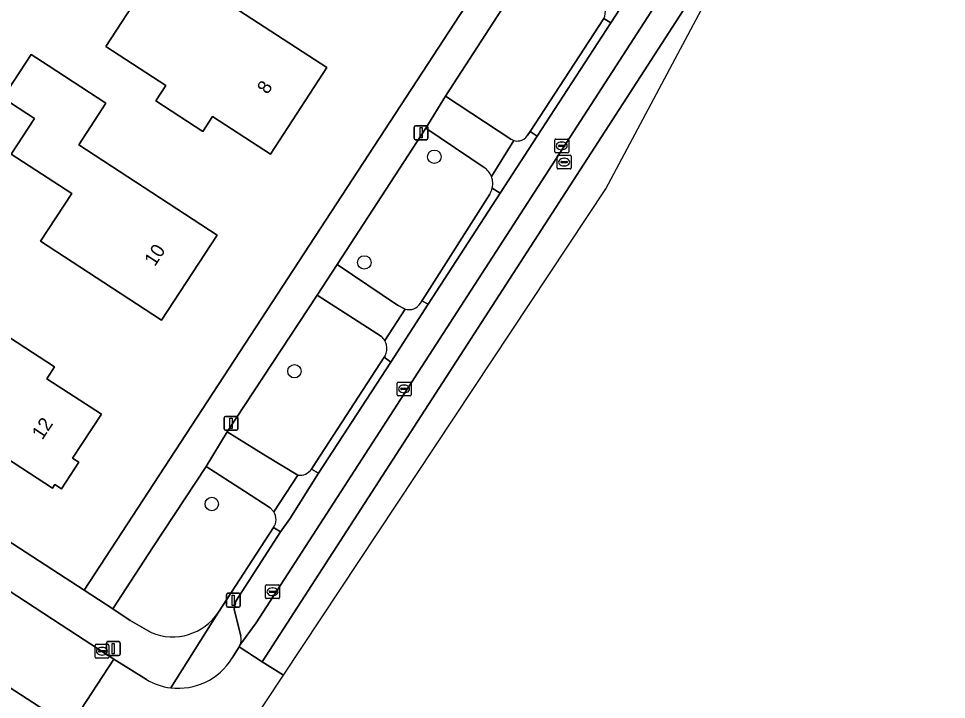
# Model space of a CAD drawing. Extents: x 161139 to 161601, y 381708 to 382245.
# Drawn here: x 161518.7 to 161586, y 382032.9 to 382082.4 of the extents above; entities that cross this region are included whole.
import ezdxf

# ---------------------------------------------------------------- set-up
doc = ezdxf.new("R2010")
doc.units = 0
for name, color, linetype in [('IMGEO_Boom', 7, 'Continuous'), ('IMGEO_Erf', 7, 'Continuous'), ('IMGEO_Groenvoorziening', 7, 'Continuous'), ('IMGEO_Kolk', 7, 'Continuous'), ('IMGEO_Lichtmast', 7, 'Continuous'), ('IMGEO_Pand', 7, 'Continuous'), ('IMGEO_Pand_nummerreeks', 7, 'Continuous'), ('IMGEO_Parkeervlak_open', 7, 'Continuous'), ('IMGEO_Rijbaan_lokaal_gesloten', 7, 'Continuous'), ('IMGEO_Rijbaan_lokaal_open', 7, 'Continuous'), ('IMGEO_Rioolput', 7, 'Continuous'), ('IMGEO_Voetpad_open', 7, 'Continuous')]:
    doc.layers.add(name, color=color, linetype=linetype)

msp = doc.modelspace()

# ---------------------------------------------------------------- linework, layer by layer
at = {"layer": 'IMGEO_Boom'}
for centre in [(161548.856, 382072.342), (161543.772, 382064.666), (161538.702, 382056.761), (161532.7, 382047.114)]:
    msp.add_circle(centre, 0.489, dxfattribs=at)
at = {"layer": 'IMGEO_Erf'}
msp.add_lwpolyline([(161553.295, 382144.911), (161544.61, 382147.101), (161500, 382158.072), (161477.956, 382163.494), (161457.897, 382168.303), (161418.52, 382178.097), (161389.844, 382185.251), (161387.058, 382185.651), (161384.186, 382184.996), (161381.949, 382183.375), (161380.259, 382181.034), (161377.586, 382172.934), (161374.321, 382163.969), (161372.26, 382158.835), (161369.98, 382153.637), (161365.084, 382143.565), (161365.175, 382143.293), (161389.855, 382127.317), (161408.789, 382114.947), (161450.498, 382088.211), (161500, 382056.07), (161523.437, 382040.853), (161561.628, 382099.383), (161581.409, 382129.761)], dxfattribs=at)
for points in [[(161527.701, 382084.489), (161521.198, 382088.726), (161524.545, 382093.864), (161525.651, 382093.143), (161529.841, 382090.414), (161527.88, 382087.405), (161541.06, 382078.818), (161536.96, 382072.525), (161532.764, 382075.259), (161532.059, 382074.178), (161528.63, 382076.412), (161529.353, 382077.522), (161525.007, 382080.354)], [(161525.013, 382076.229), (161523.049, 382073.199), (161533.095, 382066.653), (161529.061, 382060.463), (161524.873, 382063.195), (161520.269, 382066.197), (161522.531, 382069.665), (161518.135, 382072.533), (161519.823, 382075.12), (161517.521, 382076.623), (161519.575, 382079.772), (161520.824, 382078.958)], [(161513.814, 382065.857), (161512.023, 382063.108), (161521.288, 382057.068), (161520.733, 382056.215), (161524.682, 382053.642), (161522.592, 382050.435), (161523.042, 382050.142), (161521.792, 382048.223), (161521.315, 382048.534), (161521.136, 382048.26), (161512.05, 382054.18), (161513.345, 382056.167), (161510.877, 382057.775), (161511.727, 382059.08), (161510.091, 382060.146), (161509.99, 382059.992), (161504.545, 382063.541), (161505.105, 382064.4), (161502.144, 382066.33), (161505.406, 382071.336), (161508.368, 382069.406)]]:
    msp.add_lwpolyline(points, close=True, dxfattribs=at)
at = {"layer": 'IMGEO_Groenvoorziening'}
for points in [[(161560.731, 382083.685), (161556.061, 382086.613), (161549.678, 382076.751), (161554.422, 382073.613)], [(161555.605, 382073.86), (161555.805, 382074.166), (161561.16, 382082.381)], [(161552.488, 382071.564), (161548.238, 382074.428), (161541.805, 382064.505), (161546.19, 382061.555), (161546.737, 382061.267)], [(161547.846, 382061.711), (161547.959, 382061.886), (161548.022, 382061.982), (161552.884, 382069.618)], [(161545.028, 382059.277), (161540.355, 382062.295), (161533.813, 382052.367), (161536.622, 382050.604), (161538.946, 382049.208)], [(161539.95, 382049.657), (161540.282, 382050.166), (161545.221, 382057.781), (161545.289, 382057.886)], [(161537.207, 382046.547), (161536.938, 382046.844), (161535.064, 382048.048), (161532.291, 382049.829), (161528.456, 382043.995), (161525.518, 382039.495), (161526.784, 382038.653), (161528.309, 382037.772)], [(161533.184, 382039.253), (161537.192, 382045.404)]]:
    msp.add_lwpolyline(points, dxfattribs=at)
for centre, radius, start, end in [((161560.344, 382082.836), 0.935, 330.87903, 17.06204), ((161554.905, 382074.414), 0.935, 238.91578, 253.55001), ((161554.881, 382074.367), 0.883, 254.13744, 281.46792), ((161554.889, 382074.356), 0.871, 281.1415, 325.31688), ((161551.671, 382070.392), 1.429, 20.73963, 55.11747), ((161551.663, 382070.381), 1.44, 7.97325, 21.03293), ((161551.649, 382070.382), 1.452, 328.26453, 347.19705), ((161551.615, 382070.388), 1.487, 347.26233, 7.46271), ((161546.998, 382062.222), 0.99, 254.73036, 328.90808), ((161544.234, 382058.419), 1.169, 28.84853, 47.22454), ((161544.246, 382058.412), 1.162, 13.02195, 29.42536), ((161544.201, 382058.408), 1.207, 334.38025, 12.73192), ((161539.075, 382050.267), 1.067, 263.0652, 325.12425), ((161536.289, 382045.987), 1.075, 327.13152, 31.36474), ((161529.854, 382041.45), 3.989, 247.21393, 326.58309)]:
    msp.add_arc(centre, radius, start, end, dxfattribs=at)
at = {"layer": 'IMGEO_Kolk'}
for p, q in [((161557.611, 382072.704), (161557.611, 382073.556)), ((161557.686, 382073.63), (161558.538, 382073.63)), ((161558.099, 382073.41), (161558.124, 382073.41)), ((161558.612, 382073.556), (161558.612, 382072.704)), ((161557.87, 382073.124), (161557.87, 382073.136)), ((161558.308, 382073.087), (161557.91, 382073.087)), ((161557.913, 382073.173), (161558.311, 382073.173)), ((161558.122, 382072.85), (161558.097, 382072.85)), ((161558.354, 382073.136), (161558.354, 382073.124)), ((161558.538, 382072.63), (161557.686, 382072.63)), ((161546.165, 382055.049), (161546.165, 382055.901)), ((161546.24, 382055.975), (161547.092, 382055.975)), ((161547.166, 382055.901), (161547.166, 382055.049)), ((161546.424, 382055.469), (161546.424, 382055.481)), ((161546.862, 382055.432), (161546.464, 382055.432)), ((161546.467, 382055.518), (161546.865, 382055.518)), ((161546.676, 382055.195), (161546.651, 382055.195)), ((161546.653, 382055.755), (161546.678, 382055.755)), ((161546.908, 382055.481), (161546.908, 382055.469)), ((161547.092, 382054.975), (161546.24, 382054.975)), ((161536.607, 382040.314), (161536.607, 382041.166)), ((161536.682, 382041.24), (161537.534, 382041.24)), ((161537.095, 382041.02), (161537.12, 382041.02)), ((161537.608, 382041.166), (161537.608, 382040.314)), ((161536.866, 382040.734), (161536.866, 382040.746)), ((161537.304, 382040.697), (161536.906, 382040.697)), ((161536.909, 382040.783), (161537.307, 382040.783)), ((161537.118, 382040.46), (161537.093, 382040.46)), ((161537.35, 382040.746), (161537.35, 382040.734)), ((161537.534, 382040.24), (161536.682, 382040.24)), ((161524.224, 382035.995), (161524.224, 382036.847)), ((161524.299, 382036.921), (161525.151, 382036.921)), ((161524.483, 382036.415), (161524.483, 382036.427)), ((161524.921, 382036.378), (161524.523, 382036.378)), ((161524.526, 382036.464), (161524.924, 382036.464)), ((161524.712, 382036.701), (161524.737, 382036.701)), ((161524.967, 382036.427), (161524.967, 382036.415)), ((161525.225, 382036.847), (161525.225, 382035.995)), ((161525.151, 382035.921), (161524.299, 382035.921)), ((161524.735, 382036.141), (161524.71, 382036.141))]:
    msp.add_line(p, q, dxfattribs=at)
for points in [[(161557.611, 382072.704), (161557.611, 382073.556)], [(161557.686, 382073.63), (161558.538, 382073.63)], [(161558.612, 382073.556), (161558.612, 382072.704)], [(161558.538, 382072.63), (161557.686, 382072.63)], [(161546.165, 382055.049), (161546.165, 382055.901)], [(161546.24, 382055.975), (161547.092, 382055.975)], [(161547.166, 382055.901), (161547.166, 382055.049)], [(161547.092, 382054.975), (161546.24, 382054.975)], [(161536.607, 382040.314), (161536.607, 382041.166)], [(161536.682, 382041.24), (161537.534, 382041.24)], [(161537.608, 382041.166), (161537.608, 382040.314)], [(161537.534, 382040.24), (161536.682, 382040.24)], [(161524.224, 382035.995), (161524.224, 382036.847)], [(161524.299, 382036.921), (161525.151, 382036.921)], [(161525.225, 382036.847), (161525.225, 382035.995)], [(161525.151, 382035.921), (161524.299, 382035.921)]]:
    msp.add_lwpolyline(points, dxfattribs=at)
for centre, radius, start, end in [((161557.688, 382073.554), 0.0765, 91.55205, 178.44795), ((161557.688, 382073.554), 0.0765, 91.55205, 178.44795), ((161558.536, 382073.554), 0.0765, 1.55205, 88.44795), ((161558.536, 382073.554), 0.0765, 1.55205, 88.44795), ((161557.688, 382072.706), 0.0765, 181.55205, 268.44795), ((161557.688, 382072.706), 0.0765, 181.55205, 268.44795), ((161557.91, 382073.133), 0.0403, 85.87752, 175.75265), ((161557.907, 382073.123), 0.0366, 178.93798, 274.71019), ((161558.311, 382073.13), 0.043, 264.86636, 352.45326), ((161558.315, 382073.135), 0.0386, 1.73085, 96.63898), ((161558.536, 382072.706), 0.0765, 271.55205, 358.44795), ((161558.536, 382072.706), 0.0765, 271.55205, 358.44795), ((161546.242, 382055.899), 0.0765, 91.55205, 178.44795), ((161546.242, 382055.899), 0.0765, 91.55205, 178.44795), ((161547.09, 382055.899), 0.0765, 1.55205, 88.44795), ((161547.09, 382055.899), 0.0765, 1.55205, 88.44795), ((161546.464, 382055.478), 0.0403, 85.87752, 175.75265), ((161546.461, 382055.468), 0.0366, 178.93798, 274.71019), ((161546.865, 382055.475), 0.043, 264.86636, 352.45326), ((161546.869, 382055.48), 0.0386, 1.73085, 96.63898), ((161546.242, 382055.051), 0.0765, 181.55205, 268.44795), ((161546.242, 382055.051), 0.0765, 181.55205, 268.44795), ((161547.09, 382055.051), 0.0765, 271.55205, 358.44795), ((161547.09, 382055.051), 0.0765, 271.55205, 358.44795), ((161536.684, 382041.164), 0.0765, 91.55205, 178.44795), ((161536.684, 382041.164), 0.0765, 91.55205, 178.44795), ((161537.532, 382041.164), 0.0765, 1.55205, 88.44795), ((161537.532, 382041.164), 0.0765, 1.55205, 88.44795), ((161536.684, 382040.316), 0.0765, 181.55205, 268.44795), ((161536.684, 382040.316), 0.0765, 181.55205, 268.44795), ((161536.906, 382040.743), 0.0403, 85.87752, 175.75265), ((161536.903, 382040.733), 0.0366, 178.93798, 274.71019), ((161537.307, 382040.74), 0.043, 264.86636, 352.45326), ((161537.311, 382040.745), 0.0386, 1.73085, 96.63898), ((161537.532, 382040.316), 0.0765, 271.55205, 358.44795), ((161537.532, 382040.316), 0.0765, 271.55205, 358.44795), ((161524.301, 382036.845), 0.0765, 91.55205, 178.44795), ((161524.301, 382036.845), 0.0765, 91.55205, 178.44795), ((161524.523, 382036.424), 0.0403, 85.87752, 175.75265), ((161524.52, 382036.414), 0.0366, 178.93798, 274.71019), ((161524.924, 382036.421), 0.043, 264.86636, 352.45326), ((161524.928, 382036.426), 0.0386, 1.73085, 96.63898), ((161525.149, 382036.845), 0.0765, 1.55205, 88.44795), ((161525.149, 382036.845), 0.0765, 1.55205, 88.44795), ((161524.301, 382035.997), 0.0765, 181.55205, 268.44795), ((161524.301, 382035.997), 0.0765, 181.55205, 268.44795), ((161525.149, 382035.997), 0.0765, 271.55205, 358.44795), ((161525.149, 382035.997), 0.0765, 271.55205, 358.44795)]:
    msp.add_arc(centre, radius, start, end, dxfattribs=at)
for centre, major_axis, ratio, start_param, end_param in [((161558.098, 382073.13), (-0.387, 0.002), 0.722429, 4.712389, 7.853982), ((161558.123, 382073.13), (-0.39, 0.002), 0.717154, 1.570796, 4.712389), ((161546.652, 382055.475), (-0.387, 0.002), 0.722429, 4.712389, 7.853982), ((161546.677, 382055.475), (-0.39, 0.002), 0.717154, 1.570796, 4.712389), ((161537.094, 382040.74), (-0.387, 0.002), 0.722429, 4.712389, 7.853982), ((161537.119, 382040.74), (-0.39, 0.002), 0.717154, 1.570796, 4.712389), ((161524.711, 382036.421), (-0.387, 0.002), 0.722429, 4.712389, 7.853982), ((161524.736, 382036.421), (-0.39, 0.002), 0.717154, 1.570796, 4.712389)]:
    msp.add_ellipse(centre, major_axis=major_axis, ratio=ratio, start_param=start_param, end_param=end_param, dxfattribs=at)
at = {"layer": 'IMGEO_Lichtmast'}
for p, q in [((161547.399, 382073.681), (161547.399, 382074.481)), ((161547.399, 382074.481), (161547.399, 382073.681)), ((161547.499, 382074.581), (161548.289, 382074.581)), ((161548.289, 382074.581), (161547.499, 382074.581)), ((161548.389, 382074.481), (161548.389, 382073.681)), ((161548.389, 382073.681), (161548.389, 382074.481)), ((161548.289, 382073.581), (161547.499, 382073.581)), ((161547.499, 382073.581), (161548.289, 382073.581)), ((161533.599, 382052.575), (161533.599, 382053.375)), ((161533.599, 382053.375), (161533.599, 382052.575)), ((161533.699, 382053.475), (161534.489, 382053.475)), ((161534.489, 382053.475), (161533.699, 382053.475)), ((161534.589, 382053.375), (161534.589, 382052.575)), ((161534.589, 382052.575), (161534.589, 382053.375)), ((161534.489, 382052.475), (161533.699, 382052.475)), ((161533.699, 382052.475), (161534.489, 382052.475)), ((161533.766, 382039.727), (161533.766, 382040.527)), ((161533.766, 382040.527), (161533.766, 382039.727)), ((161533.866, 382040.627), (161534.656, 382040.627)), ((161534.656, 382040.627), (161533.866, 382040.627)), ((161534.756, 382040.527), (161534.756, 382039.727)), ((161534.756, 382039.727), (161534.756, 382040.527)), ((161534.656, 382039.627), (161533.866, 382039.627)), ((161533.866, 382039.627), (161534.656, 382039.627)), ((161525.052, 382036.216), (161525.052, 382037.016)), ((161525.052, 382037.016), (161525.052, 382036.216)), ((161525.152, 382037.116), (161525.942, 382037.116)), ((161525.942, 382037.116), (161525.152, 382037.116)), ((161526.042, 382037.016), (161526.042, 382036.216)), ((161526.042, 382036.216), (161526.042, 382037.016)), ((161525.942, 382036.116), (161525.152, 382036.116)), ((161525.152, 382036.116), (161525.942, 382036.116))]:
    msp.add_line(p, q, dxfattribs=at)
for points in [[(161547.819, 382074.456), (161547.969, 382074.456), (161547.969, 382073.706), (161547.819, 382073.706), (161547.819, 382074.456)], [(161534.019, 382053.35), (161534.169, 382053.35), (161534.169, 382052.6), (161534.019, 382052.6), (161534.019, 382053.35)], [(161534.186, 382040.502), (161534.336, 382040.502), (161534.336, 382039.752), (161534.186, 382039.752), (161534.186, 382040.502)], [(161525.472, 382036.991), (161525.622, 382036.991), (161525.622, 382036.241), (161525.472, 382036.241), (161525.472, 382036.991)]]:
    msp.add_lwpolyline(points, dxfattribs=at)
for centre, start, end in [((161547.499, 382074.481), 90, 180), ((161547.499, 382074.481), 90, 180), ((161548.289, 382074.481), 0, 90), ((161548.289, 382074.481), 360, 90), ((161547.499, 382073.681), 180, 270), ((161547.499, 382073.681), 180, 270), ((161548.289, 382073.681), 270, 0), ((161548.289, 382073.681), 270, 0), ((161533.699, 382053.375), 90, 180), ((161533.699, 382053.375), 90, 180), ((161534.489, 382053.375), 0, 90), ((161534.489, 382053.375), 360, 90), ((161533.699, 382052.575), 180, 270), ((161533.699, 382052.575), 180, 270), ((161534.489, 382052.575), 270, 0), ((161534.489, 382052.575), 270, 0), ((161533.866, 382040.527), 90, 180), ((161533.866, 382040.527), 90, 180), ((161534.656, 382040.527), 0, 90), ((161534.656, 382040.527), 360, 90), ((161533.866, 382039.727), 180, 270), ((161533.866, 382039.727), 180, 270), ((161534.656, 382039.727), 270, 0), ((161534.656, 382039.727), 270, 0), ((161525.152, 382037.016), 90, 180), ((161525.152, 382037.016), 90, 180), ((161525.942, 382037.016), 0, 90), ((161525.942, 382037.016), 360, 90), ((161525.152, 382036.216), 180, 270), ((161525.152, 382036.216), 180, 270), ((161525.942, 382036.216), 270, 0), ((161525.942, 382036.216), 270, 0)]:
    msp.add_arc(centre, 0.1, start, end, dxfattribs=at)
at = {"layer": 'IMGEO_Pand'}
for points in [[(161525.007, 382080.354), (161529.353, 382077.522), (161528.63, 382076.412), (161532.059, 382074.178), (161532.764, 382075.259), (161536.96, 382072.525), (161541.06, 382078.818), (161527.88, 382087.405), (161529.841, 382090.414), (161525.651, 382093.143), (161524.545, 382093.864), (161521.198, 382088.726), (161527.701, 382084.489)], [(161524.873, 382063.195), (161529.061, 382060.463), (161533.095, 382066.653), (161523.049, 382073.199), (161525.013, 382076.229), (161520.824, 382078.958), (161519.575, 382079.772), (161517.521, 382076.623), (161519.823, 382075.12), (161518.135, 382072.533), (161522.531, 382069.665), (161520.269, 382066.197)], [(161512.023, 382063.108), (161513.814, 382065.857), (161508.368, 382069.406), (161505.406, 382071.336), (161502.144, 382066.33), (161505.105, 382064.4), (161504.545, 382063.541), (161509.99, 382059.992), (161510.091, 382060.146), (161511.727, 382059.08), (161510.877, 382057.775), (161513.345, 382056.167), (161512.05, 382054.18), (161521.136, 382048.26), (161521.315, 382048.534), (161521.792, 382048.223), (161523.042, 382050.142), (161522.592, 382050.435), (161524.682, 382053.642), (161520.733, 382056.215), (161521.288, 382057.068)]]:
    msp.add_lwpolyline(points, close=True, dxfattribs=at)
at = {"layer": 'IMGEO_Parkeervlak_open'}
for points in [[(161574.099, 382099.179), (161575.329, 382102.253), (161573.302, 382103.064), (161573.086, 382102.543), (161571.379, 382098.431), (161570.865, 382097.191), (161569.158, 382093.992), (161568.512, 382092.854), (161566.951, 382090.262), (161564.239, 382086.032), (161561.667, 382082.065), (161556.335, 382073.842), (161553.645, 382069.693), (161548.411, 382061.62), (161545.69, 382057.424), (161540.456, 382049.35), (161538.374, 382046.036), (161537.696, 382045.093), (161534.437, 382040.067), (161534.33, 382039.471), (161534.799, 382037.517)], [(161534.744, 382036.848), (161535.916, 382038.476), (161568.691, 382089.227)]]:
    msp.add_lwpolyline(points, dxfattribs=at)
msp.add_arc((161533.989, 382037.247), 0.854, 332.15727, 18.44304, dxfattribs=at)
at = {"layer": 'IMGEO_Rijbaan_lokaal_gesloten'}
msp.add_lwpolyline([(161572.916, 382096.506), (161568.691, 382089.227), (161535.916, 382038.476), (161534.744, 382036.848), (161534.678, 382036.739), (161536.35, 382035.66), (161571.794, 382090.515)], dxfattribs=at)
at = {"layer": 'IMGEO_Rijbaan_lokaal_open'}
for points in [[(161571.794, 382090.515), (161536.35, 382035.66), (161537.898, 382034.67), (161561.301, 382070.022), (161583.53, 382111.715), (161586.04, 382116.528)], [(161510.796, 382038.454), (161522.385, 382030.943), (161525.596, 382035.854), (161521.765, 382038.348), (161512.078, 382044.654)], [(161528.454, 382020.403), (161537.898, 382034.67), (161536.35, 382035.66), (161534.678, 382036.739), (161534.166, 382035.893)], [(161527.949, 382034.358), (161525.596, 382035.854), (161522.385, 382030.943), (161524.371, 382029.618)]]:
    msp.add_lwpolyline(points, dxfattribs=at)
for centre, radius, start, end in [((161530.271, 382038.316), 4.587, 263.08011, 328.11728), ((161530.267, 382038.315), 4.586, 239.63862, 263.12265)]:
    msp.add_arc(centre, radius, start, end, dxfattribs=at)
at = {"layer": 'IMGEO_Rioolput'}
for p, q in [((161557.783, 382071.527), (161557.783, 382072.379)), ((161557.858, 382072.453), (161558.71, 382072.453)), ((161558.042, 382071.947), (161558.042, 382071.959)), ((161558.085, 382071.996), (161558.483, 382071.996)), ((161558.271, 382072.233), (161558.296, 382072.233)), ((161558.526, 382071.959), (161558.526, 382071.947)), ((161558.784, 382072.379), (161558.784, 382071.527)), ((161558.71, 382071.453), (161557.858, 382071.453)), ((161558.48, 382071.91), (161558.082, 382071.91)), ((161558.294, 382071.673), (161558.269, 382071.673))]:
    msp.add_line(p, q, dxfattribs=at)
for points in [[(161557.783, 382071.527), (161557.783, 382072.379)], [(161557.858, 382072.453), (161558.71, 382072.453)], [(161558.784, 382072.379), (161558.784, 382071.527)], [(161558.71, 382071.453), (161557.858, 382071.453)]]:
    msp.add_lwpolyline(points, dxfattribs=at)
for centre, radius, start, end in [((161557.86, 382072.377), 0.0765, 91.55205, 178.44795), ((161557.86, 382072.377), 0.0765, 91.55205, 178.44795), ((161558.082, 382071.956), 0.0403, 85.87752, 175.75265), ((161558.487, 382071.958), 0.0386, 1.73085, 96.63898), ((161558.708, 382072.377), 0.0765, 1.55205, 88.44795), ((161558.708, 382072.377), 0.0765, 1.55205, 88.44795), ((161557.86, 382071.529), 0.0765, 181.55205, 268.44795), ((161557.86, 382071.529), 0.0765, 181.55205, 268.44795), ((161558.079, 382071.946), 0.0366, 178.93798, 274.71019), ((161558.483, 382071.953), 0.043, 264.86636, 352.45326), ((161558.708, 382071.529), 0.0765, 271.55205, 358.44795), ((161558.708, 382071.529), 0.0765, 271.55205, 358.44795)]:
    msp.add_arc(centre, radius, start, end, dxfattribs=at)
for centre, major_axis, ratio, start_param, end_param in [((161558.27, 382071.953), (-0.387, 0.002), 0.722429, 4.712389, 7.853982), ((161558.295, 382071.953), (-0.39, 0.002), 0.717154, 1.570796, 4.712389)]:
    msp.add_ellipse(centre, major_axis=major_axis, ratio=ratio, start_param=start_param, end_param=end_param, dxfattribs=at)
at = {"layer": 'IMGEO_Voetpad_open'}
for points in [[(161581.409, 382129.761), (161561.628, 382099.383), (161523.437, 382040.853), (161525.518, 382039.495), (161528.456, 382043.995), (161532.291, 382049.829), (161533.813, 382052.367), (161540.355, 382062.295), (161541.805, 382064.505), (161548.238, 382074.428), (161549.678, 382076.751), (161556.061, 382086.613), (161557.579, 382088.971), (161563.831, 382098.367), (161565.463, 382100.982), (161566.592, 382102.722), (161568.38, 382105.476), (161581.267, 382125.334)], [(161403.197, 382115.21), (161416.21, 382106.739), (161420.597, 382103.968), (161426.931, 382099.82), (161440.905, 382090.804), (161444.055, 382088.754), (161453.24, 382082.778), (161460.192, 382078.284), (161467.324, 382073.702), (161468.287, 382073.003), (161471.488, 382070.983), (161480.028, 382065.466), (161483.251, 382063.426), (161485.554, 382061.86), (161494.669, 382055.998), (161498.469, 382053.534), (161512.078, 382044.654), (161521.765, 382038.348), (161525.596, 382035.854), (161527.949, 382034.358)], [(161528.309, 382037.772), (161526.784, 382038.653), (161525.518, 382039.495), (161523.437, 382040.853), (161500, 382056.07), (161450.498, 382088.211)], [(161561.16, 382082.381), (161561.667, 382082.065), (161564.239, 382086.032)], [(161549.678, 382076.751), (161548.238, 382074.428), (161552.488, 382071.564)], [(161554.422, 382073.613), (161549.678, 382076.751)], [(161553.065, 382070.06), (161553.645, 382069.693), (161556.335, 382073.842), (161555.805, 382074.166), (161555.605, 382073.86)], [(161554.64, 382073.517), (161553.007, 382070.898)], [(161553.007, 382070.898), (161554.64, 382073.517)], [(161552.884, 382069.618), (161548.022, 382061.982), (161547.959, 382061.886), (161548.411, 382061.62), (161553.645, 382069.693), (161553.065, 382070.06)], [(161541.805, 382064.505), (161540.355, 382062.295), (161545.028, 382059.277)], [(161545.258, 382058.983), (161546.737, 382061.267), (161546.19, 382061.555), (161541.805, 382064.505)], [(161545.289, 382057.886), (161545.221, 382057.781), (161545.69, 382057.424), (161548.411, 382061.62), (161547.959, 382061.886), (161547.846, 382061.711)], [(161546.737, 382061.267), (161545.258, 382058.983)], [(161537.192, 382045.404), (161537.696, 382045.093), (161538.374, 382046.036), (161540.456, 382049.35), (161539.95, 382049.657)], [(161538.946, 382049.208), (161537.207, 382046.547)], [(161534.799, 382037.517), (161534.33, 382039.471), (161534.437, 382040.067), (161537.696, 382045.093), (161537.192, 382045.404), (161533.184, 382039.253), (161533.151, 382039.185), (161529.718, 382033.762)], [(161529.718, 382033.762), (161533.151, 382039.185), (161533.184, 382039.253)], [(161524.371, 382029.618), (161522.385, 382030.943), (161510.796, 382038.454)], [(161534.166, 382035.893), (161534.678, 382036.739)], [(161534.678, 382036.739), (161534.744, 382036.848)]]:
    msp.add_lwpolyline(points, dxfattribs=at)
for points in [[(161556.335, 382073.842), (161561.667, 382082.065), (161561.16, 382082.381), (161555.805, 382074.166)], [(161540.456, 382049.35), (161545.69, 382057.424), (161545.221, 382057.781), (161540.282, 382050.166), (161539.95, 382049.657)], [(161536.622, 382050.604), (161533.813, 382052.367), (161532.291, 382049.829), (161535.064, 382048.048), (161536.938, 382046.844), (161537.207, 382046.547), (161538.946, 382049.208)]]:
    msp.add_lwpolyline(points, close=True, dxfattribs=at)
for centre, radius, start, end in [((161560.344, 382082.836), 0.935, 330.87903, 17.06204), ((161554.905, 382074.414), 0.935, 238.91578, 253.55001), ((161554.881, 382074.367), 0.883, 254.13744, 281.46792), ((161554.889, 382074.356), 0.871, 281.1415, 325.31688), ((161551.671, 382070.392), 1.429, 20.73963, 55.11747), ((161551.663, 382070.381), 1.44, 7.97325, 21.03293), ((161551.649, 382070.382), 1.452, 328.26453, 347.19705), ((161551.615, 382070.388), 1.487, 347.26233, 7.46271), ((161546.998, 382062.222), 0.99, 254.73036, 328.90808), ((161544.234, 382058.419), 1.169, 28.84853, 47.22454), ((161544.246, 382058.412), 1.162, 13.02195, 29.42536), ((161544.201, 382058.408), 1.207, 334.38025, 12.73192), ((161539.075, 382050.267), 1.067, 263.0652, 325.12425), ((161536.289, 382045.987), 1.075, 327.13152, 31.36474), ((161529.854, 382041.45), 3.989, 247.21393, 326.58309), ((161533.989, 382037.247), 0.854, 332.15727, 18.44304), ((161530.271, 382038.316), 4.587, 263.08011, 328.11728), ((161530.267, 382038.315), 4.586, 239.63862, 263.12265)]:
    msp.add_arc(centre, radius, start, end, dxfattribs=at)

# ---------------------------------------------------------------- texts
at = {"layer": 'IMGEO_Pand_nummerreeks'}
for s, rotation, p in [('8', 56.91505, (161536.75, 382076.82)), ('10', 56.90786, (161528.566, 382064.32)), ('12', 56.61969, (161520.398, 382051.721))]:
    msp.add_text(s, height=1, rotation=rotation, dxfattribs=at).set_placement(p)

doc.saveas('drawing.dxf')
